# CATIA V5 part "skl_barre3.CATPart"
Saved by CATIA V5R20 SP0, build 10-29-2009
Part number: skl_barre3
Publications: "Barre_3", "Axe_Pivot_b3b2", "Axe_Pivot_B"
Bounding box of the stored display mesh (mm): x -159.748 to 0, y -440 to 0, z 0 to 20
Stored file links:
  C:\Users\Matthieu\Desktop\IFMA\Cours 2A\Thinkmotion\skl_barre3.CATPart
  C:\Users\Matthieu\Desktop\IFMA\Cours 2A\Thinkmotion\skl_IAO_bis.CATProduct
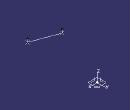
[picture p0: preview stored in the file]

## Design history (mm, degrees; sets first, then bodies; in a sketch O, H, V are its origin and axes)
AxisSystem1: origin (0, 0, 0), X (1, 0, 0), Y (0, 1, 0), Z (0, 0, 1)
Set1
  Point1 "Point.D": linked copy from another document
  Point2 "Point.B": linked copy from another document
  Plane1 "Plan_Ref": linked copy from another document
Body1 (main body)
  Line1 "Barre_3": type PtPt, FirstPoint Point1, SecondPoint Point2
  Line2 "Axe_Pivot_b3b2": type Normal, RefPoint Point1, RefSkin Plane1, Start 0, End 20
  Line3 "Axe_Pivot_B": type Normal, RefPoint Point2, RefSkin Plane1, Start 0, End 20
